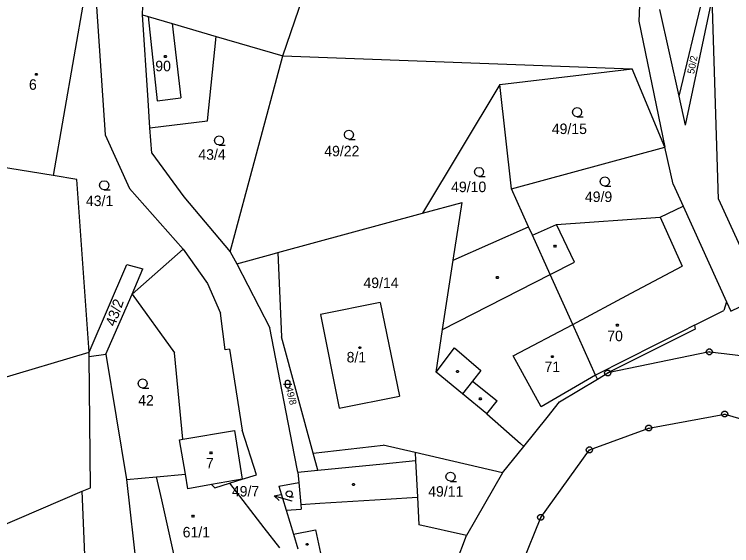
# Model space of a CAD drawing. Extents: x -780000 to -777378, y -1011169 to -1009297.
# Drawn here: x -779102.6 to -778986.4, y -1010210.7 to -1010124.6 of the extents above; entities that cross this region are included whole.
import ezdxf

# ---------------------------------------------------------------- set-up
doc = ezdxf.new("R2010")
doc.units = 0
for name, color, linetype in [('Default', 7, 'Continuous'), ('KN_HRANICE', 7, 'Continuous'), ('KN_KULTURY', 7, 'Continuous'), ('KN_PARCELY', 7, 'Continuous'), ('KN_SLUCKY', 7, 'Continuous')]:
    doc.layers.add(name, color=color, linetype=linetype)

# ---------------------------------------------------------------- blocks, each defined once
blk = doc.blocks.new('304')
at = {"layer": 'Default'}
blk.add_lwpolyline([(0, 0), (-0.38, 0.1), (-0.65, 0.37), (-0.75, 0.74), (-0.65, 1.11), (-0.38, 1.38), (-0.01, 1.48), (0.36, 1.38), (0.63, 1.11), (0.73, 0.73), (0.63, 0.35), (0.36, 0.08), (-0.02, -0.02), (0.98, -0.02)], dxfattribs=at)
blk = doc.blocks.new('316')
at = {"layer": 'Default'}
for points in [[(-0.5, 1.5), (-0.4, 1.79), (-0.15, 1.97), (0.16, 1.97), (0.41, 1.79), (0.51, 1.5), (0.51, 0.5), (0.41, 0.21), (0.16, 0.03), (-0.15, 0.03), (-0.4, 0.21), (-0.5, 0.5), (-0.5, 1.5)], [(-1, 1), (0.27, 1), (1, 1)]]:
    blk.add_lwpolyline(points, dxfattribs=at)
blk = doc.blocks.new('NAHRADNI_SYMBOL')
at = {"layer": 'Default'}
blk.add_lwpolyline([(0.09, 0.15), (0.18, 0), (0.09, -0.15), (-0.09, -0.15), (-0.18, 0), (-0.09, 0.15), (0.09, 0.15)], dxfattribs=at)
blk = doc.blocks.new('10292')
at = {"layer": 'Default'}
blk.add_line((0, 3), (0, 0), dxfattribs=at)
blk.add_lwpolyline([(-0.5, 2), (0, 3), (0.5, 2)], dxfattribs=at)
blk = doc.blocks.new('402')
at = {"layer": 'Default'}
blk.add_lwpolyline([(0.09, 0.15), (0.18, 0), (0.09, -0.15), (-0.09, -0.15), (-0.18, 0), (-0.09, 0.15), (0.09, 0.15)], dxfattribs=at)
blk = doc.blocks.new('105')
at = {"layer": 'Default'}
blk.add_line((-0.12, 0), (0.12, 0), dxfattribs=at)
blk.add_lwpolyline([(0.15, 0.48), (0.4, 0.3), (0.5, 0.01), (0.4, -0.28), (0.15, -0.46), (-0.16, -0.46), (-0.41, -0.28), (-0.51, 0.01), (-0.41, 0.3), (-0.16, 0.48), (0.15, 0.48)], dxfattribs=at)

msp = doc.modelspace()

# ---------------------------------------------------------------- linework, layer by layer
at = {"layer": 'KN_HRANICE'}
for p, q in [((-779000.52, -1010098.75), (-779001.45, -1010125.72)), ((-779059.16, -1010131.37), (-779049.6, -1010103.69)), ((-779081.9, -1010124.73), (-779081.62, -1010119.49)), ((-778990.45, -1010119.1), (-778994.99, -1010137.88)), ((-779091.18, -1010121.13), (-779096.36, -1010150.77)), ((-778989.56, -1010121.87), (-778993.95, -1010142.6)), ((-778988.54, -1010154.56), (-778989.56, -1010121.87)), ((-779089.32, -1010123.35), (-779087.92, -1010144.17)), ((-778998.08, -1010123.85), (-778994.99, -1010137.88)), ((-779081.9, -1010124.73), (-779080.97, -1010125)), ((-779080.96, -1010138.56), (-779081.9, -1010124.73)), ((-779080.97, -1010125), (-779077.09, -1010126.13)), ((-779077.09, -1010126.13), (-779069.96, -1010128.21)), ((-779001.45, -1010125.72), (-778997.25, -1010146.17)), ((-779071.34, -1010141.88), (-779069.96, -1010128.21)), ((-779069.96, -1010128.21), (-779059.16, -1010131.37)), ((-779067.67, -1010163.14), (-779059.16, -1010131.37)), ((-779059.16, -1010131.37), (-779002.53, -1010133.47)), ((-779023.96, -1010136), (-779002.53, -1010133.47)), ((-778997.25, -1010146.17), (-779002.53, -1010133.47)), ((-779023.96, -1010136), (-779036.53, -1010156.87)), ((-779022.06, -1010152.93), (-779023.96, -1010136)), ((-778994.99, -1010137.88), (-778993.95, -1010142.6)), ((-779080.66, -1010143.03), (-779080.96, -1010138.56)), ((-779080.66, -1010143.03), (-779071.34, -1010141.88)), ((-779080.38, -1010147.12), (-779080.66, -1010143.03)), ((-779087.92, -1010144.17), (-779083.99, -1010152.87)), ((-779022.06, -1010152.93), (-778997.25, -1010146.17)), ((-778995.89, -1010152.14), (-778997.25, -1010146.17)), ((-779080.38, -1010147.12), (-779075.16, -1010154.2)), ((-779096.36, -1010150.77), (-779108.53, -1010148.76)), ((-779092.51, -1010151.41), (-779096.36, -1010150.77)), ((-779090.53, -1010179.36), (-779092.51, -1010151.41)), ((-778995.89, -1010152.14), (-778994.26, -1010155.74)), ((-779083.99, -1010152.87), (-779075.29, -1010162.7)), ((-779019.31, -1010159.04), (-779022.06, -1010152.93)), ((-779075.16, -1010154.2), (-779067.67, -1010163.14)), ((-778988.54, -1010154.56), (-778981.44, -1010170.24)), ((-779036.53, -1010156.87), (-779030.09, -1010155.12)), ((-779031.52, -1010164.45), (-779030.09, -1010155.12)), ((-778998.02, -1010157.51), (-778994.26, -1010155.74)), ((-778994.26, -1010155.74), (-778987.25, -1010171.2)), ((-779059.96, -1010163.24), (-779036.53, -1010156.87)), ((-779014.8, -1010158.67), (-778998.02, -1010157.51)), ((-779031.52, -1010164.45), (-779019.31, -1010159.04)), ((-779018.68, -1010160.43), (-779019.31, -1010159.04)), ((-779018.68, -1010160.43), (-779014.8, -1010158.67)), ((-779015.8, -1010166.81), (-779018.68, -1010160.43)), ((-779083.57, -1010169.95), (-779075.29, -1010162.7)), ((-779075.29, -1010162.7), (-779071.35, -1010168.24)), ((-779067.67, -1010163.14), (-779066.59, -1010165.05)), ((-779066.59, -1010165.05), (-779060.89, -1010163.49)), ((-779060.89, -1010163.49), (-779059.96, -1010163.24)), ((-779059.96, -1010163.24), (-779059.34, -1010176.89)), ((-779066.59, -1010165.05), (-779061.23, -1010175.43)), ((-779033.24, -1010175.69), (-779031.52, -1010164.45)), ((-779090.53, -1010179.36), (-779084.42, -1010165.17)), ((-779084.42, -1010165.17), (-779081.81, -1010165.89)), ((-779083.57, -1010169.95), (-779081.81, -1010165.89)), ((-779012.17, -1010174.86), (-779015.8, -1010166.81)), ((-779071.35, -1010168.24), (-779069.24, -1010173.07)), ((-779087.81, -1010179.7), (-779083.57, -1010169.95)), ((-779083.57, -1010169.95), (-779076.68, -1010179.47)), ((-778986.55, -1010172.74), (-778981.44, -1010170.24)), ((-779043.34, -1010171.33), (-779053.06, -1010173.29)), ((-779043.34, -1010171.33), (-779040.25, -1010186.48)), ((-778987.25, -1010171.2), (-778987.68, -1010172.63)), ((-778987.25, -1010171.2), (-778986.55, -1010172.74)), ((-779068.46, -1010178.97), (-779069.24, -1010173.07)), ((-779053.06, -1010173.29), (-779050, -1010188.42)), ((-778992.44, -1010175.02), (-778987.68, -1010172.63)), ((-779057.23, -1010196.04), (-779061.23, -1010175.43)), ((-779008.46, -1010183.09), (-779012.17, -1010174.86)), ((-778992.32, -1010175.62), (-778994.25, -1010176.59)), ((-778992.44, -1010175.02), (-778992.32, -1010175.62)), ((-779034.3, -1010182.59), (-779033.24, -1010175.69)), ((-778994.25, -1010176.59), (-778998.36, -1010178.66)), ((-779054.24, -1010195.71), (-779059.34, -1010176.89)), ((-779067.77, -1010178.88), (-779068.46, -1010178.97)), ((-779067.77, -1010178.88), (-779065.75, -1010191.98)), ((-778998.36, -1010178.66), (-779006.48, -1010182.74)), ((-779127.44, -1010190.39), (-779090.53, -1010179.36)), ((-779090.52, -1010180.07), (-779090.53, -1010179.36)), ((-779090.52, -1010180.07), (-779087.81, -1010179.7)), ((-779090.29, -1010201.34), (-779090.52, -1010180.07)), ((-779087.81, -1010179.7), (-779084.45, -1010200.01)), ((-779075.35, -1010193.49), (-779076.68, -1010179.47)), ((-778990.02, -1010179.33), (-779006.48, -1010182.74)), ((-778990.02, -1010179.33), (-778987.62, -1010179.6)), ((-778987.62, -1010179.6), (-778970.48, -1010181.53)), ((-779030.01, -1010186.12), (-779034.3, -1010182.59)), ((-779014.29, -1010187.42), (-779008.17, -1010183.75)), ((-779008.17, -1010183.75), (-779008.46, -1010183.09)), ((-779008.17, -1010183.75), (-779006.48, -1010182.74)), ((-779050, -1010188.42), (-779040.25, -1010186.48)), ((-779026.06, -1010189.37), (-779030.01, -1010186.12)), ((-779016.32, -1010189.95), (-779014.29, -1010187.42)), ((-779026.06, -1010189.37), (-779020.62, -1010194.19)), ((-778999.84, -1010191.68), (-778987.54, -1010189.4)), ((-778987.54, -1010189.4), (-778972.6, -1010193.75)), ((-779020.09, -1010194.66), (-779016.32, -1010189.95)), ((-779009.45, -1010195.21), (-778999.84, -1010191.68)), ((-779063.41, -1010199.24), (-779065.75, -1010191.98)), ((-779075.89, -1010193.58), (-779075.35, -1010193.49)), ((-779074.93, -1010199.16), (-779075.89, -1010193.58)), ((-779020.62, -1010194.19), (-779020.09, -1010194.66)), ((-779054.24, -1010195.71), (-779042.86, -1010194.45)), ((-779037.72, -1010195.64), (-779042.86, -1010194.45)), ((-779023.53, -1010198.94), (-779020.09, -1010194.66)), ((-779017.34, -1010206.13), (-779009.45, -1010195.21)), ((-779056.69, -1010198.83), (-779057.23, -1010196.04)), ((-779053.48, -1010198.51), (-779054.24, -1010195.71)), ((-779023.53, -1010198.94), (-779037.72, -1010195.64)), ((-779037.72, -1010195.64), (-779037.65, -1010196.93)), ((-779037.65, -1010196.93), (-779037.33, -1010202.84)), ((-779056.69, -1010198.83), (-779053.48, -1010198.51)), ((-779056.69, -1010198.83), (-779056.55, -1010200.46)), ((-779084.45, -1010200.01), (-779079.59, -1010199.58)), ((-779079.59, -1010199.58), (-779074.93, -1010199.16)), ((-779078.76, -1010203.29), (-779079.59, -1010199.58)), ((-779074.53, -1010201.5), (-779074.93, -1010199.16)), ((-779067.78, -1010200.61), (-779065.7, -1010199.95)), ((-779065.7, -1010199.95), (-779063.41, -1010199.24)), ((-779023.53, -1010198.94), (-779029.4, -1010209.06)), ((-779070.67, -1010200.83), (-779074.53, -1010201.5)), ((-779070.67, -1010200.83), (-779070.18, -1010201.36)), ((-779070.18, -1010201.36), (-779067.78, -1010200.61)), ((-779067.78, -1010200.61), (-779062.19, -1010207.85)), ((-779059.79, -1010201.08), (-779056.55, -1010200.46)), ((-779059.79, -1010201.08), (-779058.6, -1010204.99)), ((-779056.55, -1010200.46), (-779056.24, -1010204.04)), ((-779106.91, -1010208.39), (-779091.64, -1010201.91)), ((-779091.64, -1010201.91), (-779090.29, -1010201.34)), ((-779089.99, -1010242.37), (-779091.64, -1010201.91)), ((-779076.2, -1010214.76), (-779078.76, -1010203.29)), ((-779037.33, -1010202.84), (-779037.09, -1010207.36)), ((-779056.24, -1010204.04), (-779056.17, -1010204.79)), ((-779058.6, -1010204.99), (-779056.17, -1010204.79)), ((-779058.6, -1010204.99), (-779057.43, -1010208.85)), ((-779023.92, -1010222.47), (-779017.34, -1010206.13)), ((-779062.19, -1010207.85), (-779059.7, -1010211.07)), ((-779029.4, -1010209.06), (-779037.09, -1010207.36)), ((-779057.43, -1010208.85), (-779056.71, -1010211.24)), ((-779033.8, -1010220.65), (-779029.4, -1010209.06))]:
    msp.add_line(p, q, dxfattribs=at)
msp.add_lwpolyline([(-779084.45, -1010200.01), (-779081.11, -1010229.82), (-779079.62, -1010236.77)], dxfattribs=at)
at = {"layer": 'KN_PARCELY'}
msp.add_line((-779057.66, -1010203.49), (-779057.69, -1010203.48), dxfattribs=at)
at = {"layer": 'KN_SLUCKY'}
for p, q in [((-779080.97, -1010125), (-779079.51, -1010138.63)), ((-779077.09, -1010126.13), (-779075.69, -1010138.16)), ((-779079.51, -1010138.63), (-779075.69, -1010138.16)), ((-778998.02, -1010157.51), (-778994.45, -1010165.45)), ((-779011.87, -1010164.81), (-779014.8, -1010158.67)), ((-779015.8, -1010166.81), (-779011.87, -1010164.81)), ((-779002.7, -1010169.83), (-778994.45, -1010165.45)), ((-779033.24, -1010175.69), (-779015.8, -1010166.81)), ((-779012.17, -1010174.86), (-779002.7, -1010169.83)), ((-779021.79, -1010179.97), (-779012.17, -1010174.86)), ((-778992.44, -1010175.02), (-778994.55, -1010176.08)), ((-778994.55, -1010176.08), (-778998.62, -1010178.13)), ((-779034.3, -1010182.59), (-779031.34, -1010178.65)), ((-779031.34, -1010178.65), (-779027.03, -1010182.36)), ((-778998.62, -1010178.13), (-779008.46, -1010183.09)), ((-779017.26, -1010188.23), (-779021.79, -1010179.97)), ((-779027.03, -1010182.36), (-779028.4, -1010184.09)), ((-779008.46, -1010183.09), (-779017.26, -1010188.23)), ((-779028.4, -1010184.09), (-779030.01, -1010186.12)), ((-779028.4, -1010184.09), (-779024.42, -1010187.27)), ((-779026.06, -1010189.37), (-779024.42, -1010187.27)), ((-779075.35, -1010193.49), (-779066.99, -1010192.05)), ((-779066.99, -1010192.05), (-779065.7, -1010199.95)), ((-779053.48, -1010198.51), (-779042.9, -1010197.45)), ((-779042.9, -1010197.45), (-779037.65, -1010196.93)), ((-779065.7, -1010199.95), (-779070.67, -1010200.83)), ((-779053.16, -1010203.85), (-779042.47, -1010203.17)), ((-779042.47, -1010203.17), (-779037.33, -1010202.84)), ((-779056.24, -1010204.04), (-779053.16, -1010203.85)), ((-779057.43, -1010208.85), (-779053.86, -1010208.15)), ((-779053.86, -1010208.15), (-779053.04, -1010211.92))]:
    msp.add_line(p, q, dxfattribs=at)

# ---------------------------------------------------------------- block references
at = {"layer": 'KN_KULTURY'}
for name, p in [('402', (-779078.18, -1010131.47)), ('402', (-779099.06, -1010134.35)), ('304', (-779011.45, -1010141.23)), ('304', (-779048.42, -1010144.87)), ('304', (-779069.46, -1010145.8)), ('304', (-779027.34, -1010150.91)), ('304', (-779006.96, -1010152.46)), ('304', (-779088.08, -1010153.07)), ('402', (-779015.03, -1010162.21)), ('402', (-779024.39, -1010167.26)), ('402', (-779004.95, -1010175)), ('402', (-779046.66, -1010178.63)), ('402', (-779015.48, -1010180.1)), ('402', (-779030.84, -1010182.51)), ('304', (-779081.84, -1010185.18)), ('402', (-779027.12, -1010186.92)), ('402', (-779070.78, -1010195.69)), ('304', (-779031.96, -1010200.28)), ('402', (-779047.68, -1010200.82)), ('NAHRADNI_SYMBOL', (-779073.69, -1010205.95)), ('402', (-779055.19, -1010210.5))]:
    msp.add_blockref(name, p, dxfattribs=at)
at = {"layer": 'KN_KULTURY', "xscale": 0.67, "yscale": 0.67}
for name, p in [('316', (-779058.36, -1010185.2)), ('304', (-779058.09, -1010202.81))]:
    msp.add_blockref(name, p, dxfattribs=at)
at = {"layer": 'KN_PARCELY'}
for p in [(-778990.02, -1010179.33), (-779006.48, -1010182.74), (-778987.54, -1010189.4), (-778999.84, -1010191.68), (-779009.45, -1010195.21), (-779017.34, -1010206.13)]:
    msp.add_blockref('105', p, dxfattribs=at)
at = {"layer": 'KN_PARCELY', "rotation": 73.395894}
msp.add_blockref('10292', (-779057.69, -1010203.48), dxfattribs=at)

# ---------------------------------------------------------------- texts
at = {"layer": 'KN_PARCELY'}
for s, height, rotation, p in [('50/2', 1.14, 78.553, (-778992.51, -1010134.36)), ('43/2', 1.7, 70.932, (-779086.32, -1010175.31)), ('49/8', 1.14, 284.015, (-779058.68, -1010185.14))]:
    msp.add_text(s, height=height, rotation=rotation, dxfattribs=at).set_placement(p)
for s, height, p in [('90', 1.7, (-779079.8, -1010133.86)), ('6', 1.7, (-779100.27, -1010136.86)), ('49/15', 1.7, (-779015.55, -1010144.03)), ('43/4', 1.7, (-779072.82, -1010148.19)), ('49/22', 1.7, (-779052.42, -1010147.64)), ('49/10', 1.7, (-779031.87, -1010153.44)), ('49/9', 1.7, (-779010.19, -1010155.04)), ('43/1', 1.7, (-779091.04, -1010155.7)), ('49/14', 1.7, (-779046.07, -1010168.98)), ('70', 1.7, (-779006.57, -1010177.59)), ('8/1', 1.7, (-779048.8, -1010181.03)), ('71', 1.7, (-779016.73, -1010182.59)), ('42', 1.7, (-779082.57, -1010188.02)), ('7', 1.7, (-779071.59, -1010198.2)), ('49/7', 1.7, (-779067.39, -1010202.75)), ('49/11', 1.7, (-779035.58, -1010202.78)), ('49/7', 0.1, (-779057.86, -1010203.49)), ('61/1', 1.7, (-779075.36, -1010209.38))]:
    msp.add_text(s, height=height, dxfattribs=at).set_placement(p)

doc.saveas('drawing.dxf')
